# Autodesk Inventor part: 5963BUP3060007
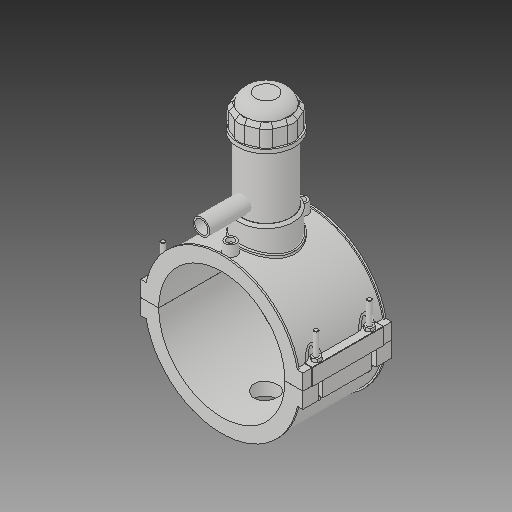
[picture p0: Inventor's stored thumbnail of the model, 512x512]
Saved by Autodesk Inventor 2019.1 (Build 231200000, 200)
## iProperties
Created: 2017-07
Part Number: 5963BUP3060007
Material: Generic
Description: PLASSON TAPPING SADDLE 6''IPS x 3/4''CTS
Document SubType Name: Modeling
Designer: KIM
Density: 1 g/cm^3
Appearance: Default
Author: KIM
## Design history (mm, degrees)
derived "5963BBP_5963BUP.ipt"
feature "Solid1::5963BBP_5963BUP.ipt"
feature "Solid2::5963BBP_5963BUP.ipt"
feature "Solid3::5963BBP_5963BUP.ipt"
tag "TaggingFeature1"
body "Solid1"
body "Solid2"
body "Solid3"
other parameters: "d_" = 168, "B_" = 215.9, "L_" = 118.11, "d_t" = 6, "H_2" = 177.038, "H_1" = 65.024, "d_1" = 22.1, "H_" = 86.106, "d1" = 201.6, "d148" = 2.52, "d160" = 2.52, "d169" = 3.2805, "d192" = 6.9984, "d0" = 168, "d2" = 215.9, "d3" = 42, "d4" = 118.11, "d5" = 0, "d6" = 0.1, "d8" = 0, "d19" = 6, "d20" = 6, "d21" = 70.866, "d23" = 0, "d24" = 35.433, "d26" = 0, "d27" = 3, "d28" = 3, "d29" = 3, "d30" = 56, "d31" = 6, "d32" = 0, "d33" = 0, "d34" = 0.6, "d40" = 104.832, "d41" = 75.6, "d43" = 0, "d45" = 0, "d47" = 171.666, "d70" = 15, "d72" = 0, "d73" = 6, "d75" = 5, "d76" = 0, "d77" = 8.4, "d78" = 114, "d79" = 15, "d80" = 47.244, "d82" = 5 deg, "d84" = 4, "d85" = 14, "d86" = 0, "d87" = 3, "d88" = 0, "d89" = 1, "d90" = 1, "d91" = 94.488, "d92" = 0, "d93" = 0.5, "d94" = 88.42105, "d96" = 205.632, "d97" = 2.3622, "d98" = 0, "d102" = 1.68, "d120" = 140 deg, "d121" = 24.228, "d122" = 20 deg, "d123" = 403.2, "d124" = 120.96, "d126" = 0, "d143" = 173.04, "d145" = 25.84615, "d149" = 2.52, "d150" = 28.43077, "d153" = 118.11, "d154" = 0, "d156" = 100.8, "d157" = 160 deg, "d159" = 6.72, "d161" = 2.52, "d162" = 70.866, "d163" = 0, "d164" = 84, "d167" = 16.8, "d168" = 98.34146, "d170" = 3.2805, "d172" = 0, "d173" = 1, "d175" = 84, "d176" = 20 deg, "d177" = 11.76, "d178" = 33.6, "d180" = 0, "d183" = 13.44, "d184" = 9.408, "d185" = 38.38575, "d186" = 38.38575, "d187" = 100.8, "d188" = 10.08, "d189" = 11.76, "d190" = 0, "d191" = 151.2, "d193" = 6.9984, "d194" = 4.13385, "d195" = 90 deg, "d197" = 0, "d199" = 0, "d200" = 16.8, "d202" = 0, "d203" = 177.038, "d204" = 71.82, "d205" = 52.92, "d206" = 64.26, "d207" = 132.7785, "d208" = 138.08964, "d209" = 164.64534, "d210" = 65.016, "d211" = 75.6, "d212" = 60.48, "d213" = 48.5766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
